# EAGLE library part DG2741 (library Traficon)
Dual analog SPST switch
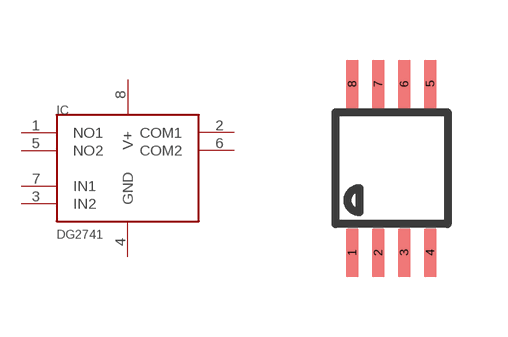
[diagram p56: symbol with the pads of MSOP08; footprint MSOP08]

Designator prefix IC

## DG2741  [MSOP08]
1  NO1
2  COM1
3  IN2
4  GND
5  NO2
6  COM2
7  IN1
8  V+

## Footprint MSOP08 (pad centres in mm)
Mini Small Outline Package Grid 0.5mm
smd 0.3 x 1.2: 1 -0.976,-2.113; 2 -0.326,-2.113; 3 0.324,-2.113; 4 0.974,-2.113; 5 0.974,2.112; 6 0.324,2.112; 7 -0.326,2.112; 8 -0.976,2.112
